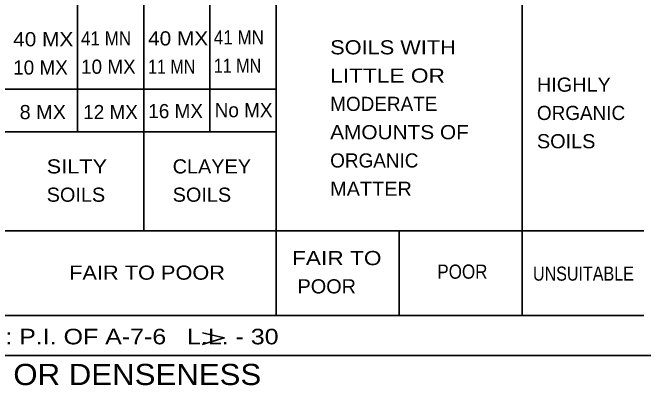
# Model space of a CAD drawing. Extents: x 2137492.6 to 2137529.1, y 2137475.8 to 2137563.
# Drawn here: x 2137497.407 to 2137501.868, y 2137551.13 to 2137553.765 of the extents above; entities that cross this region are included whole.
import ezdxf
from ezdxf.enums import TextEntityAlignment as Align

# ---------------------------------------------------------------- set-up
doc = ezdxf.new("R2010")
doc.units = 0
doc.header["$LTSCALE"] = 0.04
doc.layers.add('1', color=7, linetype='Continuous', lineweight=35)

msp = doc.modelspace()

# ---------------------------------------------------------------- linework, layer by layer
at = {"layer": '1'}
for p, q in [((2137499.271, 2137556.123), (2137499.271, 2137551.631)), ((2137497.867, 2137552.923), (2137497.867, 2137555.623)), ((2137498.803, 2137552.923), (2137498.803, 2137555.623)), ((2137501.011, 2137551.631), (2137501.011, 2137555.623)), ((2137498.335, 2137552.223), (2137498.335, 2137554.226)), ((2137493.171, 2137553.223), (2137499.271, 2137553.223)), ((2137493.171, 2137552.923), (2137499.271, 2137552.923)), ((2137493.171, 2137552.223), (2137501.871, 2137552.223)), ((2137500.141, 2137551.631), (2137500.141, 2137552.22)), ((2137493.171, 2137551.623), (2137501.871, 2137551.623)), ((2137510.771, 2137551.34), (2137493.171, 2137551.34))]:
    msp.add_line(p, q, dxfattribs=at)
msp.add_lwpolyline([(2137498.751, 2137551.502), (2137498.904, 2137551.466), (2137498.747, 2137551.418)], dxfattribs=at)

# ---------------------------------------------------------------- texts
for s, height, width, p in [('40 MX', 0.1, 1.1, (2137497.411, 2137553.527)), ('41 MN', 0.1, 0.9, (2137497.891, 2137553.533)), ('40 MX', 0.1, 1.1, (2137498.365, 2137553.533)), ('41 MN', 0.1, 0.9, (2137498.83, 2137553.54)), ('SOILS WITH', 0.1, 1.15, (2137499.653, 2137553.47)), ('11 MN', 0.1, 0.85, (2137498.83, 2137553.34)), ('11 MN', 0.1, 0.85, (2137498.365, 2137553.333)), ('LITTLE OR', 0.1, 1.2, (2137499.653, 2137553.27)), ('HIGHLY', 0.1, 1.05, (2137501.115, 2137553.206)), ('AMOUNTS OF', 0.1, 1.1, (2137499.653, 2137552.87)), ('SOILS', 0.1, 1.05, (2137501.115, 2137552.806)), ('SILTY', 0.1, 1.15, (2137497.648, 2137552.628)), ('CLAYEY', 0.1, 1.05, (2137498.539, 2137552.628)), ('MATTER', 0.1, 1.05, (2137499.653, 2137552.47)), ('SOILS', 0.1, 1.05, (2137497.648, 2137552.428)), ('SOILS', 0.1, 1.05, (2137498.539, 2137552.428)), ('FAIR TO', 0.1, 1.2, (2137499.383, 2137551.98)), (' POOR', 0.1, 1.05, (2137499.383, 2137551.78)), ('CONSISTENCY OR DENSENESS', 0.15, 1.1, (2137495.757, 2137551.132))]:
    msp.add_text(s, height=height, dxfattribs=dict(at, width=width)).set_placement(p)
for s, p in [('10 MX', (2137497.411, 2137553.327)), ('10 MX', (2137497.891, 2137553.333)), ('MODERATE', (2137499.653, 2137553.07)), ('ORGANIC', (2137501.115, 2137553.006)), ('ORGANIC', (2137499.653, 2137552.67))]:
    msp.add_text(s, height=0.1, dxfattribs=at).set_placement(p)
for s, p in [('No MX', (2137499.0405, 2137553.026)), ('12 MX', (2137498.0995, 2137553.012)), ('16 MX', (2137498.56, 2137553.019))]:
    msp.add_text(s, height=0.1, dxfattribs=at).set_placement(p, align=Align.CENTER)
for s, height, width, p in [('8 MX', 0.1, 1.05, (2137497.6205, 2137553.012)), ('FAIR TO POOR', 0.1, 1.15, (2137498.358, 2137551.877)), ('POOR', 0.1, 0.9, (2137500.588, 2137551.884)), ('UNSUITABLE', 0.1, 0.85, (2137501.444, 2137551.87)), ('P.I. OF A-7-5   L.L. - 30 : P.I. OF A-7-6   L.L. - 30', 0.11, 1.2, (2137497.38, 2137551.42))]:
    msp.add_text(s, height=height, dxfattribs=dict(at, width=width)).set_placement(p, align=Align.CENTER)

doc.saveas('drawing.dxf')
